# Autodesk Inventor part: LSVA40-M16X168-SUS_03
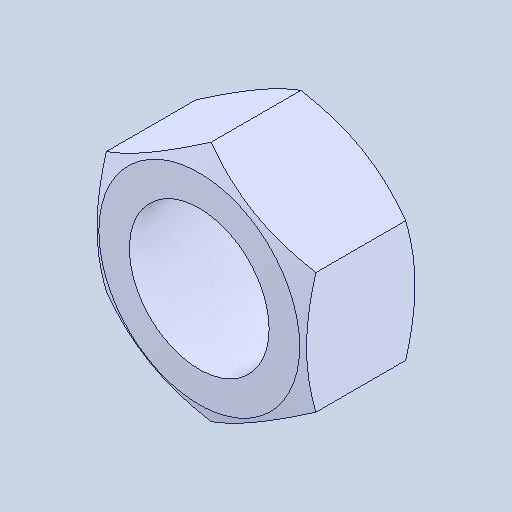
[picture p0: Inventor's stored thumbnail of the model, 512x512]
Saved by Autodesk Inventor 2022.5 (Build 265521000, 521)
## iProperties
Created: 2024-08
Part Number: LSVA40-M16X168-SUS_03
Material: 一般
Document SubType Name: Modeling
Designer: ImaoCorp
Density: 1 g/cm^3
Appearance: 既定
Author: ImaoCorp
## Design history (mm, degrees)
feature "LSVA40-M16X168-SUS_03"
node "ソリッド1"
